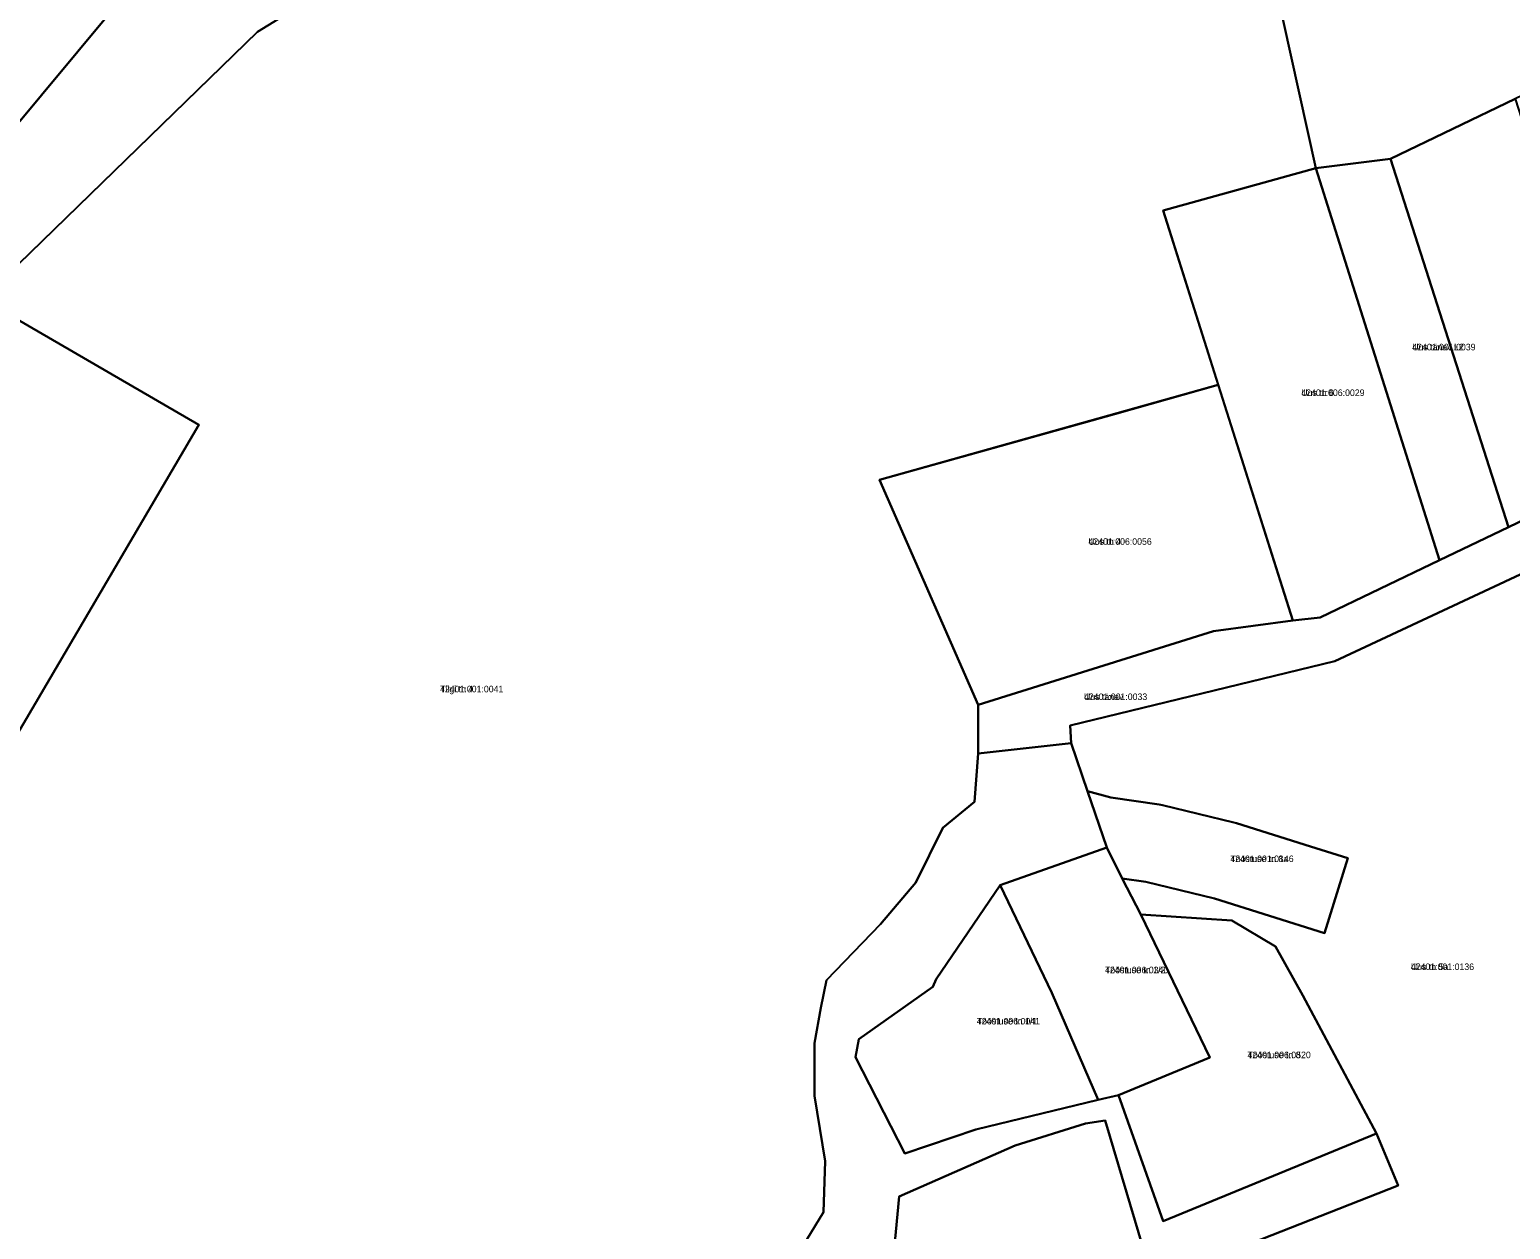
# Model space of a CAD drawing. Extents: x 595979 to 597983, y 6604231 to 6607350.
# Drawn here: x 596873.6 to 597213, y 6606558.1 to 6606833.3 of the extents above; entities that cross this region are included whole.
import ezdxf

# ---------------------------------------------------------------- set-up
doc = ezdxf.new("R2010")
doc.units = 0
for name, color, linetype in [('L_AADRESS', 7, 'Continuous'), ('PIIR', 7, 'Continuous'), ('TUNNUS', 7, 'Continuous')]:
    doc.layers.add(name, color=color, linetype=linetype)

msp = doc.modelspace()

# ---------------------------------------------------------------- linework, layer by layer
at = {"layer": 'PIIR'}
for points in [[(597380.8, 6607108.42), (597047.73, 6606904.01), (596982.1, 6606867.34), (596925.85, 6606832.78), (596862.67, 6606771.48)], [(596781.96, 6607063.97), (597021.47, 6607025.87), (597017.44, 6606900.77), (596951.46, 6606860.47), (596893.34, 6606838.71), (596841.73, 6606776.77)], [(596841.73, 6606776.77), (596893.34, 6606838.71), (596951.46, 6606860.47), (597017.44, 6606900.77), (597227.14, 6607031)], [(596840.01, 6606619.43), (596912.39, 6606742.64), (596862.67, 6606771.48), (596925.85, 6606832.78), (596982.1, 6606867.34)], [(597157.16, 6606852.69), (597168.46, 6606801.45), (597133.43, 6606791.76), (597146.09, 6606751.78), (597068.42, 6606729.98), (597091.03, 6606678.43), (597091.01, 6606667.21), (597090.21, 6606656.13), (597082.97, 6606650.2), (597076.77, 6606637.69), (597068.61, 6606628.07), (597056.28, 6606615.29), (597054.97, 6606608.95), (597053.53, 6606600.85), (597053.53, 6606588.7), (597055.98, 6606573.73), (597055.58, 6606562.03), (597039.22, 6606535.24)], [(597250.77, 6606724.9), (597172.79, 6606688.42), (597112.15, 6606673.69), (597112.33, 6606669.62), (597091.01, 6606667.21), (597091.03, 6606678.43), (597144.96, 6606695.34), (597163.19, 6606697.76), (597169.46, 6606698.41), (597196.8, 6606711.57), (597212.63, 6606719.19), (597241.28, 6606732.97)], [(597144.75, 6606551.47), (597187.35, 6606568.17), (597182.32, 6606580.07), (597165.43, 6606611.74), (597159.16, 6606622.98), (597149.19, 6606628.93), (597128.3, 6606630.3), (597124.01, 6606638.58), (597129.47, 6606637.78), (597145.18, 6606634), (597170.41, 6606626.08), (597175.81, 6606643.25), (597167.22, 6606645.95), (597150.28, 6606651.27), (597149.68, 6606651.44), (597133.28, 6606655.37), (597132.49, 6606655.53), (597121.44, 6606657.15), (597116.1, 6606658.62), (597112.33, 6606669.62), (597112.15, 6606673.69), (597172.79, 6606688.42), (597250.77, 6606724.9)], [(597039.22, 6606535.24), (597055.58, 6606562.03), (597055.98, 6606573.73), (597053.53, 6606588.7), (597053.53, 6606600.85), (597054.97, 6606608.95), (597056.28, 6606615.29), (597068.61, 6606628.07), (597076.77, 6606637.69), (597082.97, 6606650.2), (597090.21, 6606656.13), (597091.01, 6606667.21), (597112.33, 6606669.62), (597116.1, 6606658.62), (597120.54, 6606645.67), (597096.11, 6606637.07), (597081.41, 6606615.5), (597080.62, 6606613.74), (597063.71, 6606601.74), (597062.89, 6606597.58), (597074.23, 6606575.48), (597090.52, 6606581.02), (597118.54, 6606587.81), (597123.24, 6606588.91), (597133.41, 6606560.01), (597182.32, 6606580.07), (597187.35, 6606568.17), (597144.75, 6606551.47)], [(597130.78, 6606547.35), (597120.15, 6606583.09), (597115.61, 6606582.36), (597099.55, 6606577.35), (597072.92, 6606565.63), (597071.01, 6606545.43)]]:
    msp.add_lwpolyline(points, dxfattribs=at)
for points in [[(597185.54, 6606803.62), (597168.46, 6606801.45), (597157.16, 6606852.69), (597127.58, 6606861.69), (597047.73, 6606904.01), (597380.8, 6607108.42), (597415.02, 6606900.83), (597345.38, 6606865.19), (597309.9, 6606829.23), (597300.15, 6606858.7), (597271.1, 6606844.74), (597243, 6606831.24), (597214.14, 6606817.36)], [(597214.14, 6606817.36), (597241.28, 6606732.97), (597212.63, 6606719.19), (597185.54, 6606803.62)], [(597212.63, 6606719.19), (597196.8, 6606711.57), (597168.46, 6606801.45), (597185.54, 6606803.62)], [(597168.46, 6606801.45), (597196.8, 6606711.57), (597169.46, 6606698.41), (597163.19, 6606697.76), (597133.43, 6606791.76)], [(596912.39, 6606742.64), (596840.01, 6606619.43), (596790.45, 6606648.77), (596862.67, 6606771.48)], [(597068.42, 6606729.98), (597122.27, 6606745.1), (597146.09, 6606751.78), (597163.19, 6606697.76), (597144.96, 6606695.34), (597091.03, 6606678.43)], [(597116.1, 6606658.62), (597121.44, 6606657.15), (597132.49, 6606655.53), (597133.28, 6606655.37), (597149.68, 6606651.44), (597150.28, 6606651.27), (597167.22, 6606645.95), (597175.81, 6606643.25), (597170.41, 6606626.08), (597145.18, 6606634), (597129.47, 6606637.78), (597124.01, 6606638.58), (597120.54, 6606645.67)], [(597107.9, 6606612.38), (597096.11, 6606637.07), (597120.54, 6606645.67), (597124.01, 6606638.58), (597128.3, 6606630.3), (597144.11, 6606597.5), (597123.24, 6606588.91), (597118.54, 6606587.81)], [(597090.52, 6606581.02), (597074.23, 6606575.48), (597062.89, 6606597.58), (597063.71, 6606601.74), (597080.62, 6606613.74), (597081.41, 6606615.5), (597096.11, 6606637.07), (597107.9, 6606612.38), (597118.54, 6606587.81)], [(597128.3, 6606630.3), (597149.19, 6606628.93), (597159.16, 6606622.98), (597165.43, 6606611.74), (597182.32, 6606580.07), (597133.41, 6606560.01), (597123.24, 6606588.91), (597144.11, 6606597.5)], [(597099.55, 6606577.35), (597115.61, 6606582.36), (597120.15, 6606583.09), (597130.78, 6606547.35), (597117.1, 6606525.95), (597102.13, 6606521.61), (597097.06, 6606537.41), (597085.79, 6606548.69), (597071.01, 6606545.43), (597072.92, 6606565.63)]]:
    msp.add_lwpolyline(points, close=True, dxfattribs=at)

# ---------------------------------------------------------------- texts
at = {"layer": 'L_AADRESS'}
for s, p in [('Uus tänav L2', (597190.55, 6606759.71)), ('Uus tn 6', (597165.11, 6606749.24)), ('Uus tn 4', (597116.32, 6606715.11)), ('Tiigi tn 4', (596967.68, 6606681.28)), ('Uus tänav', (597115.29, 6606679.51)), ('Tööstuse tn 8a', (597148.85, 6606642.35)), ('Tööstuse tn 1/2', (597120.11, 6606616.85)), ('Uus tn 5a', (597190.22, 6606617.59)), ('Tööstuse tn 1/1', (597090.71, 6606605.11)), ('Tööstuse tn 8', (597152.78, 6606597.37))]:
    msp.add_text(s, height=1.5, dxfattribs=at).set_placement(p)
at = {"layer": 'TUNNUS'}
for s, p in [('42401:001:0039', (597190.55, 6606759.71)), ('42401:006:0029', (597165.11, 6606749.24)), ('42401:006:0056', (597116.32, 6606715.11)), ('42401:001:0041', (596967.68, 6606681.28)), ('42401:001:0033', (597115.29, 6606679.51)), ('42401:001:0146', (597148.85, 6606642.35)), ('42401:006:0340', (597120.11, 6606616.85)), ('42401:001:0136', (597190.22, 6606617.59)), ('42401:006:0041', (597090.71, 6606605.11)), ('42401:006:0520', (597152.78, 6606597.37))]:
    msp.add_text(s, height=1.5, dxfattribs=at).set_placement(p)

doc.saveas('drawing.dxf')
